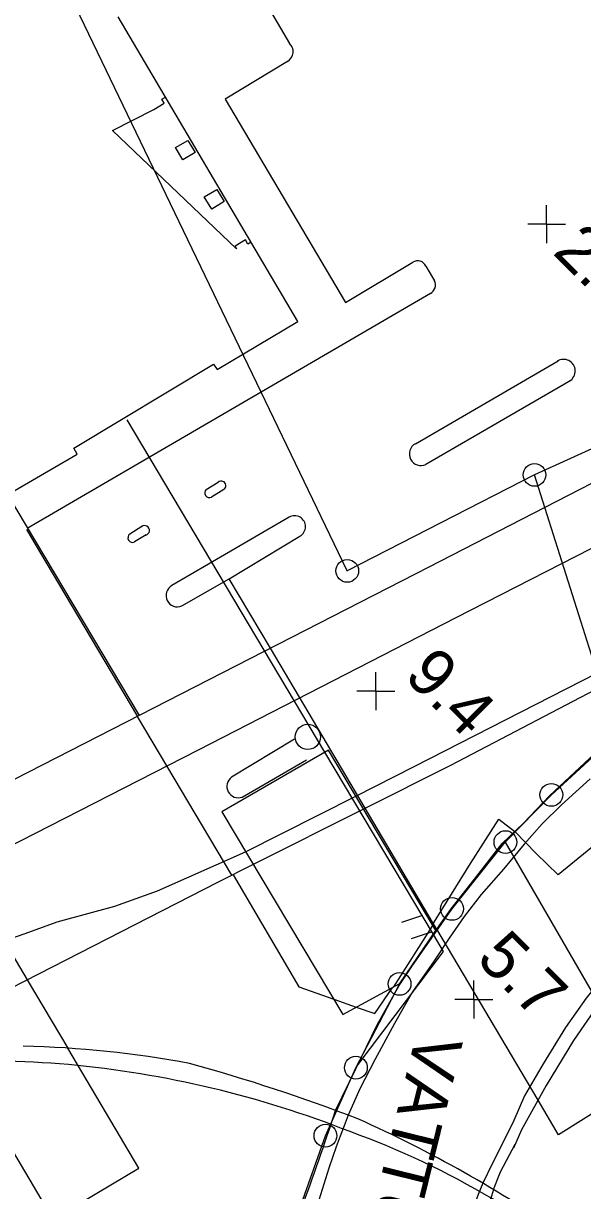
# Model space of a CAD drawing. Extents: x 1596643 to 1597288, y 13057194 to 13057957.
# Drawn here: x 1596896.9 to 1596926.3, y 13057540.5 to 13057602 of the extents above; entities that cross this region are included whole.
import ezdxf

# ---------------------------------------------------------------- set-up
doc = ezdxf.new("R2010")
doc.units = 0
for name, color, linetype in [('BAS bro ej def L', 7, 'Continuous'), ('BAS byggnad anläggning L', 7, 'Continuous'), ('BAS fastighetsgräns samfällighet L', 7, 'Continuous'), ('BAS gränspunkt P', 7, 'Continuous'), ('BAS Level 16', 7, 'Continuous'), ('BAS Level 19', 7, 'Continuous'), ('BAS Level 37', 7, 'Continuous'), ('BAS markytetext T', 7, 'Continuous'), ('BAS skärmtak L', 7, 'Continuous'), ('BAS staket plank lågt L', 7, 'Continuous'), ('BAS väg T', 7, 'Continuous'), ('BAS vägbanekant L', 7, 'Continuous'), ('BAS vägbanekant skymd L', 7, 'Continuous')]:
    doc.layers.add(name, color=color, linetype=linetype)

msp = doc.modelspace()

# ---------------------------------------------------------------- linework, layer by layer
at = {"layer": 'BAS bro ej def L'}
for points in [[(1596943.383, 13057586.288), (1596918.209, 13057573.372), (1596902.266, 13057565.204), (1596883.836, 13057555.789), (1596868.629, 13057548.018), (1596857.404, 13057542.31), (1596846.034, 13057536.411), (1596835.657, 13057531.108), (1596827.266, 13057526.827), (1596817.271, 13057521.926), (1596816.146, 13057521.371), (1596813.704, 13057520.386), (1596810.367, 13057519.363)], [(1596913.296, 13057544.769), (1596914.377, 13057546.965), (1596915.486, 13057549.268), (1596916.652, 13057551.347), (1596918.519, 13057554.127), (1596919.399, 13057555.376), (1596920.744, 13057557.097), (1596922.078, 13057558.817), (1596923.21, 13057559.89), (1596924.571, 13057561.326), (1596926.969, 13057563.551), (1596928.05, 13057564.574), (1596929.891, 13057566.176), (1596933.114, 13057568.573), (1596936.442, 13057570.4), (1596940.179, 13057572.486), (1596946.835, 13057576.211), (1596950.858, 13057578.384), (1596953.337, 13057579.805), (1596953.472, 13057580.048)], [(1596953.472, 13057580.048), (1596950.476, 13057578.704), (1596946.804, 13057576.892), (1596943.151, 13057575.1), (1596928.089, 13057567.48), (1596919.359, 13057562.929), (1596914.781, 13057560.629)], [(1596968.373, 13057578.261), (1596961.827, 13057574.867), (1596953.74, 13057570.551), (1596946.343, 13057566.846), (1596942.262, 13057564.195), (1596937.944, 13057561.203), (1596935.83, 13057559.685), (1596934.453, 13057558.595), (1596933.004, 13057557.364), (1596931.108, 13057555.498), (1596929.206, 13057553.094), (1596927.126, 13057550.316), (1596925.83, 13057548.442), (1596924.406, 13057546.082), (1596923.094, 13057543.751), (1596922.685, 13057542.791)], [(1596914.781, 13057560.629), (1596908.963, 13057557.707)], [(1596908.963, 13057557.707), (1596907.091, 13057556.766), (1596894.719, 13057550.443), (1596892.663, 13057549.443)], [(1596921.63, 13057540.603), (1596921.997, 13057541.53), (1596922.773, 13057542.998)]]:
    msp.add_lwpolyline(points, dxfattribs=at)
msp.add_circle((1596911.839, 13057564.429), 0.664, dxfattribs=at)
for centre, radius, start, end in [((1596895.7, 13057494.276), 53.885, 79.40138, 88.77393), ((1596880.351, 13057455.564), 95.094, 68.96491, 74.59554), ((1596821.119, 13057574.061), 96.719, 339.09659, 342.37079), ((1596886.889, 13057482.558), 67.647, 55.31245, 65.92546), ((1597000.567, 13057512.676), 83.732, 160.51681, 164.46611)]:
    msp.add_arc(centre, radius, start, end, dxfattribs=at)
at = {"layer": 'BAS byggnad anläggning L'}
for points in [[(1596866.704, 13057601.943), (1596867.746, 13057600.069), (1596867.47, 13057599.92), (1596868.226, 13057598.701), (1596868.431, 13057598.841), (1596869.733, 13057596.669), (1596869.426, 13057596.51), (1596870.132, 13057595.383), (1596870.45, 13057595.562), (1596881.678, 13057576.612), (1596888.388, 13057580.56), (1596892.741, 13057575.564), (1596895.189, 13057577.005), (1596895.38, 13057576.82), (1596899.692, 13057579.305), (1596899.513, 13057579.622), (1596906.87, 13057584.049), (1596907.059, 13057583.773), (1596911.31, 13057586.299), (1596901.852, 13057602.339)], [(1596908.851, 13057590.47), (1596908.675, 13057590.371), (1596908.554, 13057590.585), (1596908.006, 13057590.256), (1596908.088, 13057590.119), (1596901.555, 13057596.34), (1596903.733, 13057597.456), (1596904.273, 13057597.778), (1596904.153, 13057597.99), (1596904.349, 13057598.104)], [(1596905.255, 13057594.797), (1596904.866, 13057595.45), (1596905.525, 13057595.829), (1596905.907, 13057595.185), (1596905.255, 13057594.797)], [(1596906.779, 13057592.209), (1596906.387, 13057592.86), (1596907.043, 13057593.25), (1596907.434, 13057592.603), (1596906.779, 13057592.209)], [(1596892.425, 13057549.166), (1596890.617, 13057552.208), (1596895.129, 13057554.892), (1596897.061, 13057551.64)], [(1596897.061, 13057551.64), (1596899.196, 13057548.047)], [(1596898.432, 13057539.054), (1596892.999, 13057548.2)], [(1596898.432, 13057539.054), (1596902.944, 13057541.738), (1596899.196, 13057548.047)]]:
    msp.add_lwpolyline(points, dxfattribs=at)
at = {"layer": 'BAS fastighetsgräns samfällighet L'}
for points in [[(1596913.913, 13057573.162), (1596863.532, 13057677.717)], [(1596957.924, 13057593.7), (1596923.777, 13057578.215)], [(1596923.777, 13057578.215), (1596913.913, 13057573.162)], [(1596928.117, 13057564.535), (1596923.777, 13057578.215)], [(1596922.244, 13057558.883), (1596943.245, 13057522.631)]]:
    msp.add_lwpolyline(points, dxfattribs=at)
at = {"layer": 'BAS gränspunkt P'}
for centre, radius in [((1596923.783, 13057578.222), 0.6), ((1596923.783, 13057578.222), 0.6), ((1596923.778, 13057578.215), 0.001), ((1596923.778, 13057578.215), 0.001), ((1596913.919, 13057573.169), 0.6), ((1596913.919, 13057573.169), 0.6), ((1596913.914, 13057573.162), 0.001), ((1596913.914, 13057573.162), 0.001), ((1596924.671, 13057561.378), 0.6), ((1596924.671, 13057561.378), 0.6), ((1596924.666, 13057561.371), 0.001), ((1596924.666, 13057561.371), 0.001), ((1596922.25, 13057558.89), 0.6), ((1596922.25, 13057558.89), 0.6), ((1596922.245, 13057558.883), 0.001), ((1596922.245, 13057558.883), 0.001), ((1596919.437, 13057555.377), 0.6), ((1596919.437, 13057555.377), 0.6), ((1596919.432, 13057555.37), 0.001), ((1596919.432, 13057555.37), 0.001), ((1596916.673, 13057551.428), 0.6), ((1596916.673, 13057551.428), 0.6), ((1596916.668, 13057551.421), 0.001), ((1596916.668, 13057551.421), 0.001), ((1596914.373, 13057547.018), 0.6), ((1596914.373, 13057547.018), 0.6), ((1596914.368, 13057547.011), 0.001), ((1596914.368, 13057547.011), 0.001), ((1596912.77, 13057543.439), 0.6), ((1596912.77, 13057543.439), 0.6), ((1596912.765, 13057543.432), 0.001), ((1596912.765, 13057543.432), 0.001)]:
    msp.add_circle(centre, radius, dxfattribs=at)
at = {"layer": 'BAS Level 16'}
for p, q in [((1596924.423, 13057591.412), (1596924.423, 13057592.412)), ((1596924.423, 13057591.412), (1596924.423, 13057592.412)), ((1596924.423, 13057591.412), (1596923.423, 13057591.412)), ((1596924.423, 13057591.412), (1596923.423, 13057591.412)), ((1596924.423, 13057591.412), (1596925.423, 13057591.412)), ((1596924.423, 13057591.412), (1596924.423, 13057590.412)), ((1596924.423, 13057591.412), (1596925.423, 13057591.412)), ((1596924.423, 13057591.412), (1596924.423, 13057590.412)), ((1596915.424, 13057566.832), (1596915.424, 13057567.832)), ((1596915.424, 13057566.832), (1596915.424, 13057567.832)), ((1596915.424, 13057566.832), (1596914.424, 13057566.832)), ((1596915.424, 13057566.832), (1596914.424, 13057566.832)), ((1596915.424, 13057566.832), (1596916.424, 13057566.832)), ((1596915.424, 13057566.832), (1596915.424, 13057565.832)), ((1596915.424, 13057566.832), (1596916.424, 13057566.832)), ((1596915.424, 13057566.832), (1596915.424, 13057565.832)), ((1596920.586, 13057550.605), (1596920.586, 13057551.605)), ((1596920.586, 13057550.605), (1596920.586, 13057551.605)), ((1596920.586, 13057550.605), (1596919.586, 13057550.605)), ((1596920.586, 13057550.605), (1596919.586, 13057550.605)), ((1596920.586, 13057550.605), (1596921.586, 13057550.605)), ((1596920.586, 13057550.605), (1596920.586, 13057549.605)), ((1596920.586, 13057550.605), (1596921.586, 13057550.605)), ((1596920.586, 13057550.605), (1596920.586, 13057549.605))]:
    msp.add_line(p, q, dxfattribs=at)
at = {"layer": 'BAS Level 19'}
for p, q in [((1596917.887, 13057555.025), (1596916.782, 13057554.664)), ((1596917.887, 13057555.025), (1596916.782, 13057554.664)), ((1596918.398, 13057554.166), (1596917.294, 13057553.805)), ((1596918.398, 13057554.166), (1596917.294, 13057553.805))]:
    msp.add_line(p, q, dxfattribs=at)
for points in [[(1596902.298, 13057581.12), (1596912.726, 13057563.621)], [(1596896.012, 13057577.184), (1596902.963, 13057565.562)], [(1596907.9, 13057557.173), (1596911.368, 13057551.266), (1596913.207, 13057550.623)], [(1596918.444, 13057554.025), (1596918.974, 13057553.136), (1596914.476, 13057547.179)], [(1596914.394, 13057550.208), (1596915.378, 13057549.864)]]:
    msp.add_lwpolyline(points, dxfattribs=at)
at = {"layer": 'BAS Level 37'}
for points in [[(1596924.665, 13057561.371), (1596928.117, 13057564.535)], [(1596922.244, 13057558.883), (1596924.665, 13057561.371)], [(1596919.431, 13057555.37), (1596922.244, 13057558.883)], [(1596916.667, 13057551.421), (1596919.431, 13057555.37)], [(1596914.367, 13057547.011), (1596916.667, 13057551.421)], [(1596912.764, 13057543.432), (1596914.367, 13057547.011)], [(1596911.392, 13057539.526), (1596912.764, 13057543.432)]]:
    msp.add_lwpolyline(points, dxfattribs=at)
at = {"layer": 'BAS skärmtak L'}
msp.add_lwpolyline([(1596907.303, 13057560.478), (1596913.686, 13057549.824), (1596916.686, 13057551.452), (1596918.588, 13057554.235), (1596912.929, 13057563.739), (1596907.303, 13057560.478)], dxfattribs=at)
at = {"layer": 'BAS staket plank lågt L'}
for points in [[(1596912.726, 13057563.621), (1596918.444, 13057554.025)], [(1596913.207, 13057550.623), (1596914.394, 13057550.208)]]:
    msp.add_lwpolyline(points, dxfattribs=at)
at = {"layer": 'BAS vägbanekant L'}
for points in [[(1596919.734, 13057607.279), (1596917.673, 13057611.25), (1596908.106, 13057605.662), (1596910.878, 13057600.93)], [(1596910.774, 13057599.986), (1596907.495, 13057597.996), (1596913.829, 13057587.293)], [(1596968.373, 13057595.733), (1596951.07, 13057586.844), (1596934.686, 13057578.377), (1596919.638, 13057570.696), (1596906.067, 13057563.73), (1596892.75, 13057556.935), (1596882.725, 13057551.852), (1596869.694, 13057545.167), (1596859.148, 13057539.721), (1596850.202, 13057535.12), (1596841.053, 13057530.419), (1596829.938, 13057524.843), (1596820.555, 13057520.234), (1596817.458, 13057518.694), (1596815.33, 13057517.841), (1596812.855, 13057516.796), (1596811.578, 13057516.307)], [(1596913.829, 13057587.293), (1596917.378, 13057589.41)], [(1596918.056, 13057589.209), (1596918.514, 13057588.44)], [(1596918.297, 13057587.775), (1596897.049, 13057575.402)], [(1596917.514, 13057579.863), (1596925.038, 13057584.232)], [(1596925.692, 13057583.195), (1596925.692, 13057583.195), (1596918.066, 13057578.769)], [(1596914.372, 13057561.316), (1596917.444, 13057562.872), (1596928.682, 13057568.61), (1596938.606, 13057573.643), (1596949.945, 13057579.289), (1596957.717, 13057582.859)], [(1596968.373, 13057579.108), (1596961.429, 13057575.474), (1596955.01, 13057572.03), (1596951.137, 13057569.925), (1596946.714, 13057567.395), (1596944.085, 13057565.864), (1596941.669, 13057564.341), (1596939.507, 13057562.888), (1596936.998, 13057561.142), (1596935.152, 13057559.728), (1596933.977, 13057558.626), (1596932.324, 13057557.242), (1596930.649, 13057555.614), (1596929.934, 13057554.846), (1596928.615, 13057553.287), (1596926.498, 13057550.676), (1596925.424, 13057549.126), (1596924.235, 13057547.221), (1596923.251, 13057545.529), (1596922.696, 13057544.241), (1596922.08, 13057542.995), (1596921.577, 13057541.991), (1596921.058, 13057540.941)], [(1596906.494, 13057577.455), (1596906.494, 13057577.455), (1596907.125, 13057577.842)], [(1596907.423, 13057577.452), (1596907.423, 13057577.452), (1596906.766, 13057577.052)], [(1596910.852, 13057575.989), (1596906.617, 13057573.523)], [(1596897.013, 13057575.349), (1596898.036, 13057573.63), (1596902.867, 13057565.512)], [(1596902.464, 13057575.119), (1596903.09, 13057575.515)], [(1596903.319, 13057575.07), (1596902.716, 13057574.691)], [(1596909.867, 13057569.098), (1596907.704, 13057572.748), (1596911.425, 13057574.995)], [(1596906.617, 13057573.523), (1596904.678, 13057572.392)], [(1596905.205, 13057571.324), (1596907.704, 13057572.748)], [(1596911.142, 13057564.318), (1596907.826, 13057562.31)], [(1596908.388, 13057561.266), (1596908.388, 13057561.266), (1596910.686, 13057562.593), (1596911.768, 13057563.218)], [(1596926.719, 13057562.228), (1596925.198, 13057560.853), (1596924.187, 13057559.852), (1596923.237, 13057558.79), (1596922.143, 13057557.474), (1596920.977, 13057556.128), (1596920.077, 13057554.985), (1596919.289, 13057553.83), (1596918.5, 13057552.635), (1596917.354, 13057551.004), (1596916.411, 13057549.342), (1596915.375, 13057547.427), (1596914.574, 13057545.906), (1596913.964, 13057544.519)], [(1596918.638, 13057554.297), (1596914.862, 13057560.67)], [(1596915.105, 13057560.26), (1596915.077, 13057560.306)], [(1596918.407, 13057554.539), (1596920.409, 13057557.758), (1596921.91, 13057560.091), (1596922.753, 13057559.457)], [(1596884.037, 13057548.055), (1596892.534, 13057552.343), (1596894.887, 13057553.368), (1596897.137, 13057554.16), (1596898.643, 13057554.691), (1596901.676, 13057555.52), (1596903.926, 13057556.332), (1596908.562, 13057558.377)], [(1596915.378, 13057549.864), (1596916.319, 13057551.253)], [(1596932.074, 13057541.943), (1596928.722, 13057545.775), (1596925.048, 13057543.481), (1596923.968, 13057545.304)]]:
    msp.add_lwpolyline(points, dxfattribs=at)
for centre, radius, start, end in [((1596910.478, 13057600.497), 0.589, 300.08184, 47.26864), ((1596917.633, 13057589.025), 0.461, 23.44415, 123.52986), ((1596918.073, 13057588.216), 0.494, 296.89156, 26.96379), ((1596925.316, 13057583.69), 0.613, 300.91568, 123.5605), ((1596917.802, 13057579.322), 0.613, 118.02849, 295.51963), ((1596906.659, 13057577.273), 0.246, 132.19524, 295.83454), ((1596907.277, 13057577.653), 0.246, 305.04937, 129.716), ((1596903.241, 13057575.296), 0.256, 285.17658, 129.28941), ((1596911.145, 13057575.496), 0.574, 299.20005, 120.72388), ((1596902.614, 13057574.919), 0.25, 126.8699, 294.10223), ((1596904.966, 13057571.87), 0.596, 118.88658, 293.64039), ((1596908.176, 13057561.825), 0.598, 125.81608, 290.76916), ((1596894.227, 13057488.471), 58.92, 85.13396, 99.46488), ((1596894.219, 13057493.126), 54.285, 68.55609, 84.70877), ((1596899.166, 13057502.372), 43.887, 48.44084, 70.15464)]:
    msp.add_arc(centre, radius, start, end, dxfattribs=at)
at = {"layer": 'BAS vägbanekant skymd L'}
for points in [[(1596947.811, 13057575.992), (1596942.622, 13057571.747), (1596936.143, 13057566.285), (1596930.481, 13057561.615), (1596925.021, 13057557.177), (1596923.876, 13057558.298), (1596922.753, 13057559.457)], [(1596914.862, 13057560.67), (1596909.867, 13057569.098)], [(1596907.845, 13057557.145), (1596902.867, 13057565.512)], [(1596908.563, 13057558.374), (1596914.372, 13057561.316)], [(1596916.373, 13057551.282), (1596918.429, 13057554.503)], [(1596923.968, 13057545.304), (1596918.636, 13057554.302)]]:
    msp.add_lwpolyline(points, dxfattribs=at)
for centre, radius, start, end in [((1596972.367, 13057521.809), 62.664, 158.75177, 176.0506), ((1596960.949, 13057524.71), 43.067, 157.85939, 185.31331)]:
    msp.add_arc(centre, radius, start, end, dxfattribs=at)

# ---------------------------------------------------------------- texts
at = {"layer": 'BAS markytetext T'}
for s, p in [('2.0', (1596924.681, 13057589.894)), ('9.4', (1596916.851, 13057567.573)), ('5.7', (1596920.65, 13057552.674))]:
    msp.add_text(s, height=2.5, rotation=315, dxfattribs=at).set_placement(p)
at = {"layer": 'BAS väg T'}
msp.add_text('VATTUGATAN', height=2.5, rotation=256.14, dxfattribs=at).set_placement((1596917.586, 13057548.963))

doc.saveas('drawing.dxf')
